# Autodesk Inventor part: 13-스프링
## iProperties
Created: 2014-11
Part Number: 13-스프링
Document SubType Name: Modeling
Designer: elite
Density: 7.86 g/cm^3
Material: 강, 연강
Mass: 2.84502 g
Surface Area: 9.80054 cm^2
Volume: 0.361961 cm^3
Author: elite
